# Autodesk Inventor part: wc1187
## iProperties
Shininess: 64.0
Length Units: 11272
Angle Units: 11279
Time Units: 11290
Mass Units: 11286
Length Display Precision: 3
Angle Display Precision: 2
Compacted: True
Part Number: wc1187
Document SubType Name: Modeling
Created: 2004-08
Designer: John Blackburn
Manufacturer: Standard
Standards Organization: Custom
Density: 0.0
Volumn: 0.0
Area: 0.0
PropertySet Name: Model Information
Control State: 0
Master: False
Checked Out: False
Author: John Blackburn
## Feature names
1. Base1
